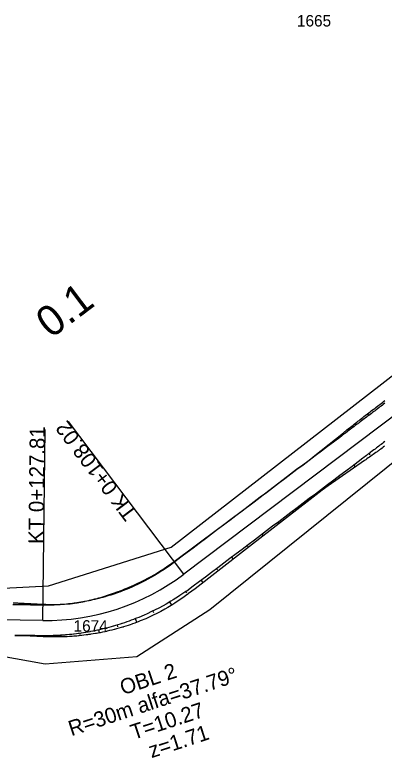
# Model space of a CAD drawing. Extents: x -583470 to -583050, y -1165714 to -1165417.
# Drawn here: x -583308.7 to -583260.4, y -1165593.5 to -1165496.2 of the extents above; entities that cross this region are included whole.
import ezdxf

# ---------------------------------------------------------------- set-up
doc = ezdxf.new("R2010")
doc.units = 0
for name, color, linetype in [('Hranice parcel', 7, 'Continuous'), ('Kabel_soucasny', 7, 'Continuous'), ('Parcelní čísla', 7, 'Continuous'), ('Rám', 7, 'Continuous'), ('Sítě', 7, 'Continuous'), ('Šrafy', 7, 'Continuous')]:
    doc.layers.add(name, color=color, linetype=linetype)

msp = doc.modelspace()

# ---------------------------------------------------------------- linework, layer by layer
at = {"layer": 'Hranice parcel'}
for points in [[(-583286.571, -1165569.38), (-583301.643, -1165549.435)], [(-583305.033, -1165575.443), (-583304.72, -1165550.445)]]:
    msp.add_lwpolyline(points, dxfattribs=at)
at = {"layer": 'Parcelní čísla'}
for p, q in [((-583232.311, -1165528.379), (-583286.571, -1165569.38)), ((-583305.033, -1165575.443), (-583329.322, -1165575.139))]:
    msp.add_line(p, q, dxfattribs=at)
msp.add_arc((-583304.657, -1165545.446), 30, 269.28237, 307.07651, dxfattribs=at)
at = {"layer": 'Rám'}
for points in [[(-583348.01, -1165573.19), (-583304.26, -1165570.92), (-583288.23, -1165565.85), (-583222.91, -1165515.13), (-583194.86, -1165515.1)], [(-583202.69, -1165538.68), (-583225.12, -1165531.51), (-583247.31, -1165545.19), (-583283.21, -1165574.06), (-583292.71, -1165580.22), (-583304.73, -1165581.14), (-583316.86, -1165578.96), (-583335.26, -1165581.29), (-583341.42, -1165583.09), (-583347.21, -1165586.62), (-583351.13, -1165592.35), (-583353.34, -1165595.85), (-583354.98, -1165601.64), (-583352.56, -1165623.43)]]:
    msp.add_lwpolyline(points, dxfattribs=at)
at = {"layer": 'Sítě'}
for points in [[(-583260.31, -1165547.029), (-583260.471, -1165547.151), (-583260.631, -1165547.273), (-583260.634, -1165547.275), (-583260.792, -1165547.394), (-583260.953, -1165547.516), (-583261.114, -1165547.637), (-583261.275, -1165547.759), (-583261.432, -1165547.878), (-583261.436, -1165547.881), (-583261.597, -1165548.002), (-583261.758, -1165548.124), (-583261.919, -1165548.246), (-583262.08, -1165548.367), (-583262.23, -1165548.48), (-583262.241, -1165548.489), (-583262.402, -1165548.611), (-583262.563, -1165548.732), (-583262.724, -1165548.854), (-583262.885, -1165548.975), (-583263.028, -1165549.083), (-583263.046, -1165549.097), (-583263.207, -1165549.219), (-583263.368, -1165549.34), (-583263.529, -1165549.462), (-583263.69, -1165549.584), (-583263.826, -1165549.686), (-583263.851, -1165549.705), (-583264.012, -1165549.827), (-583264.173, -1165549.948), (-583264.334, -1165550.07), (-583264.494, -1165550.192), (-583264.623, -1165550.289), (-583264.655, -1165550.313), (-583264.816, -1165550.435), (-583264.977, -1165550.557), (-583265.138, -1165550.678), (-583265.299, -1165550.8), (-583265.421, -1165550.892), (-583265.46, -1165550.921), (-583265.621, -1165551.043), (-583266.219, -1165551.495), (-583267.017, -1165552.098), (-583267.815, -1165552.701), (-583268.613, -1165553.303), (-583269.41, -1165553.906), (-583270.208, -1165554.509), (-583271.006, -1165555.112), (-583271.804, -1165555.715), (-583272.602, -1165556.318), (-583273.4, -1165556.921), (-583274.197, -1165557.524), (-583274.995, -1165558.127), (-583275.793, -1165558.729), (-583276.591, -1165559.332), (-583277.389, -1165559.935), (-583278.187, -1165560.538), (-583278.984, -1165561.141), (-583279.782, -1165561.744), (-583280.58, -1165562.347), (-583281.378, -1165562.95), (-583282.176, -1165563.552), (-583282.974, -1165564.155), (-583283.771, -1165564.758), (-583284.569, -1165565.361), (-583285.367, -1165565.964), (-583286.165, -1165566.567), (-583286.963, -1165567.17), (-583287.761, -1165567.773), (-583287.777, -1165567.785), (-583288.515, -1165568.324), (-583288.606, -1165568.388), (-583289.287, -1165568.849), (-583289.458, -1165568.961), (-583290.075, -1165569.349), (-583290.33, -1165569.502), (-583290.88, -1165569.821), (-583291.221, -1165570.011), (-583291.7, -1165570.267), (-583292.13, -1165570.487), (-583292.534, -1165570.685), (-583293.055, -1165570.929), (-583293.382, -1165571.075), (-583293.997, -1165571.337), (-583294.243, -1165571.437), (-583294.36, -1165571.483), (-583294.611, -1165571.581), (-583294.863, -1165571.677), (-583294.953, -1165571.71), (-583295.115, -1165571.769), (-583295.116, -1165571.77), (-583295.369, -1165571.86), (-583295.624, -1165571.948), (-583295.879, -1165572.034), (-583295.921, -1165572.048), (-583295.997, -1165572.073), (-583296.135, -1165572.117), (-583296.392, -1165572.198), (-583296.65, -1165572.276), (-583296.889, -1165572.346), (-583296.902, -1165572.35), (-583296.908, -1165572.352), (-583297.167, -1165572.425), (-583297.427, -1165572.496), (-583297.687, -1165572.564), (-583297.79, -1165572.59), (-583297.893, -1165572.616), (-583297.949, -1165572.63), (-583298.21, -1165572.693), (-583298.473, -1165572.754), (-583298.699, -1165572.804), (-583298.736, -1165572.812), (-583298.893, -1165572.846), (-583298.999, -1165572.868), (-583299.263, -1165572.921), (-583299.528, -1165572.972), (-583299.614, -1165572.988), (-583299.793, -1165573.02), (-583299.901, -1165573.039), (-583300.058, -1165573.065), (-583300.324, -1165573.108), (-583300.534, -1165573.14), (-583300.59, -1165573.149), (-583300.857, -1165573.186), (-583300.915, -1165573.194), (-583301.124, -1165573.222), (-583301.391, -1165573.254), (-583301.46, -1165573.262), (-583301.659, -1165573.285), (-583301.926, -1165573.312), (-583301.934, -1165573.313), (-583302.195, -1165573.337), (-583302.389, -1165573.353), (-583302.463, -1165573.359), (-583302.731, -1165573.379), (-583302.957, -1165573.394), (-583303, -1165573.396), (-583303.269, -1165573.411), (-583303.32, -1165573.414), (-583303.538, -1165573.423), (-583303.807, -1165573.433), (-583303.982, -1165573.437), (-583304.076, -1165573.44), (-583304.253, -1165573.443), (-583304.346, -1165573.444), (-583304.615, -1165573.446), (-583304.884, -1165573.445), (-583305.008, -1165573.443), (-583305.164, -1165573.441), (-583305.199, -1165573.441), (-583305.452, -1165573.438), (-583305.741, -1165573.434), (-583306.029, -1165573.431), (-583306.199, -1165573.428), (-583306.318, -1165573.427), (-583306.606, -1165573.423), (-583306.895, -1165573.42), (-583307.183, -1165573.416), (-583307.199, -1165573.416), (-583307.472, -1165573.412), (-583307.761, -1165573.409), (-583308.049, -1165573.405), (-583308.199, -1165573.403), (-583308.338, -1165573.402), (-583308.626, -1165573.398), (-583308.915, -1165573.394)], [(-583308.911, -1165573.139), (-583308.623, -1165573.143), (-583308.334, -1165573.152), (-583308.196, -1165573.159), (-583308.046, -1165573.167), (-583307.758, -1165573.183), (-583307.469, -1165573.199), (-583307.196, -1165573.213), (-583307.181, -1165573.214), (-583306.893, -1165573.227), (-583306.604, -1165573.24), (-583306.316, -1165573.253), (-583306.197, -1165573.259), (-583306.027, -1165573.267), (-583305.739, -1165573.281), (-583305.451, -1165573.295), (-583305.197, -1165573.308), (-583305.162, -1165573.309), (-583305.006, -1165573.317), (-583304.883, -1165573.323), (-583304.615, -1165573.332), (-583304.347, -1165573.34), (-583304.254, -1165573.341), (-583304.078, -1165573.344), (-583303.984, -1165573.345), (-583303.81, -1165573.346), (-583303.541, -1165573.345), (-583303.323, -1165573.342), (-583303.273, -1165573.342), (-583303.004, -1165573.335), (-583302.96, -1165573.334), (-583302.735, -1165573.327), (-583302.466, -1165573.315), (-583302.392, -1165573.312), (-583302.198, -1165573.301), (-583301.937, -1165573.285), (-583301.929, -1165573.284), (-583301.661, -1165573.265), (-583301.461, -1165573.249), (-583301.392, -1165573.243), (-583301.124, -1165573.218), (-583300.915, -1165573.192), (-583300.857, -1165573.183), (-583300.591, -1165573.139), (-583300.536, -1165573.13), (-583300.326, -1165573.093), (-583300.062, -1165573.044), (-583299.905, -1165573.014), (-583299.797, -1165572.993), (-583299.619, -1165572.957), (-583299.534, -1165572.939), (-583299.271, -1165572.883), (-583299.008, -1165572.824), (-583298.903, -1165572.8), (-583298.746, -1165572.763), (-583298.71, -1165572.754), (-583298.485, -1165572.7), (-583298.224, -1165572.634), (-583297.964, -1165572.566), (-583297.909, -1165572.551), (-583297.807, -1165572.523), (-583297.705, -1165572.495), (-583297.447, -1165572.421), (-583297.189, -1165572.345), (-583296.933, -1165572.266), (-583296.914, -1165572.26), (-583296.677, -1165572.185), (-583296.422, -1165572.102), (-583296.167, -1165572.016), (-583296.031, -1165571.969), (-583295.956, -1165571.943), (-583295.914, -1165571.928), (-583295.661, -1165571.838), (-583295.409, -1165571.748), (-583295.157, -1165571.656), (-583294.995, -1165571.596), (-583294.905, -1165571.562), (-583294.655, -1165571.466), (-583294.406, -1165571.368), (-583294.289, -1165571.321), (-583294.045, -1165571.22), (-583293.433, -1165570.959), (-583293.108, -1165570.814), (-583292.588, -1165570.572), (-583292.185, -1165570.376), (-583291.755, -1165570.16), (-583291.276, -1165569.909), (-583290.935, -1165569.724), (-583290.383, -1165569.413), (-583290.128, -1165569.261), (-583289.514, -1165568.874), (-583289.343, -1165568.763), (-583288.665, -1165568.305), (-583288.573, -1165568.242), (-583287.834, -1165567.709), (-583282.205, -1165563.514), (-583281.404, -1165562.915), (-583280.612, -1165562.304), (-583277.393, -1165559.93), (-583276.595, -1165559.327), (-583272.651, -1165556.253), (-583271.852, -1165555.651), (-583271.02, -1165555.094), (-583270.226, -1165554.485), (-583269.445, -1165553.86), (-583265.736, -1165550.891), (-583265.578, -1165550.765), (-583265.54, -1165550.735), (-583265.421, -1165550.639), (-583265.263, -1165550.513), (-583265.105, -1165550.388), (-583264.947, -1165550.262), (-583264.789, -1165550.137), (-583264.757, -1165550.112), (-583264.63, -1165550.012), (-583264.472, -1165549.887), (-583264.313, -1165549.762), (-583264.155, -1165549.638), (-583263.996, -1165549.513), (-583263.971, -1165549.494), (-583263.837, -1165549.389), (-583263.678, -1165549.264), (-583263.519, -1165549.14), (-583263.36, -1165549.016), (-583263.2, -1165548.893), (-583263.182, -1165548.879), (-583263.041, -1165548.769), (-583262.881, -1165548.646), (-583262.722, -1165548.522), (-583262.562, -1165548.399), (-583262.402, -1165548.276), (-583262.391, -1165548.268), (-583262.242, -1165548.153), (-583262.082, -1165548.03), (-583261.921, -1165547.908), (-583261.761, -1165547.786), (-583261.596, -1165547.66), (-583261.44, -1165547.541), (-583261.279, -1165547.419), (-583261.118, -1165547.297), (-583260.958, -1165547.176), (-583260.796, -1165547.054), (-583260.635, -1165546.933), (-583260.474, -1165546.812), (-583260.313, -1165546.691)], [(-583260.312, -1165552.045), (-583260.473, -1165552.167), (-583260.616, -1165552.275), (-583260.634, -1165552.288), (-583260.795, -1165552.41), (-583260.956, -1165552.532), (-583261.117, -1165552.653), (-583261.278, -1165552.775), (-583261.414, -1165552.878), (-583261.439, -1165552.896), (-583261.6, -1165553.018), (-583261.761, -1165553.14), (-583261.922, -1165553.261), (-583262.083, -1165553.383), (-583262.212, -1165553.48), (-583262.244, -1165553.505), (-583262.405, -1165553.626), (-583262.566, -1165553.748), (-583262.727, -1165553.87), (-583262.888, -1165553.991), (-583263.01, -1165554.083), (-583263.049, -1165554.113), (-583263.21, -1165554.234), (-583263.808, -1165554.686), (-583264.605, -1165555.289), (-583265.403, -1165555.892), (-583266.201, -1165556.495), (-583266.999, -1165557.098), (-583267.797, -1165557.701), (-583268.595, -1165558.303), (-583269.392, -1165558.906), (-583270.19, -1165559.509), (-583270.988, -1165560.112), (-583271.786, -1165560.715), (-583272.584, -1165561.318), (-583273.382, -1165561.921), (-583274.179, -1165562.524), (-583274.977, -1165563.127), (-583275.775, -1165563.729), (-583276.573, -1165564.332), (-583277.371, -1165564.935), (-583278.169, -1165565.538), (-583278.966, -1165566.141), (-583279.764, -1165566.744), (-583280.562, -1165567.347), (-583281.36, -1165567.95), (-583282.158, -1165568.552), (-583282.955, -1165569.155), (-583283.753, -1165569.758), (-583284.551, -1165570.361), (-583285.349, -1165570.964), (-583285.365, -1165570.976), (-583286.209, -1165571.592), (-583286.313, -1165571.666), (-583287.091, -1165572.193), (-583287.286, -1165572.32), (-583287.992, -1165572.763), (-583288.283, -1165572.939), (-583288.912, -1165573.304), (-583289.301, -1165573.52), (-583289.849, -1165573.813), (-583290.34, -1165574.064), (-583290.802, -1165574.291), (-583291.398, -1165574.569), (-583291.771, -1165574.736), (-583292.474, -1165575.036), (-583292.755, -1165575.15), (-583292.889, -1165575.203), (-583293.176, -1165575.315), (-583293.464, -1165575.424), (-583293.566, -1165575.462), (-583293.751, -1165575.53), (-583293.752, -1165575.53), (-583294.042, -1165575.634), (-583294.333, -1165575.734), (-583294.625, -1165575.832), (-583294.673, -1165575.848), (-583294.76, -1165575.877), (-583294.918, -1165575.927), (-583295.211, -1165576.02), (-583295.506, -1165576.109), (-583295.78, -1165576.189), (-583295.794, -1165576.194), (-583295.801, -1165576.196), (-583296.097, -1165576.279), (-583296.394, -1165576.36), (-583296.692, -1165576.438), (-583296.809, -1165576.468), (-583296.927, -1165576.498), (-583296.99, -1165576.513), (-583297.289, -1165576.586), (-583297.589, -1165576.655), (-583297.847, -1165576.713), (-583297.89, -1165576.722), (-583298.069, -1165576.76), (-583298.191, -1165576.785), (-583298.492, -1165576.846), (-583298.795, -1165576.904), (-583298.893, -1165576.922), (-583299.098, -1165576.959), (-583299.221, -1165576.98), (-583299.401, -1165577.011), (-583299.705, -1165577.06), (-583299.946, -1165577.097), (-583300.009, -1165577.106), (-583300.314, -1165577.149), (-583300.38, -1165577.158), (-583300.619, -1165577.19), (-583300.924, -1165577.227), (-583301.003, -1165577.236), (-583301.23, -1165577.262), (-583301.536, -1165577.293), (-583301.545, -1165577.294), (-583301.843, -1165577.322), (-583302.064, -1165577.34), (-583302.149, -1165577.347), (-583302.456, -1165577.37), (-583302.714, -1165577.386), (-583302.763, -1165577.389), (-583303.071, -1165577.406), (-583303.129, -1165577.409), (-583303.378, -1165577.42), (-583303.686, -1165577.431), (-583303.885, -1165577.436), (-583303.993, -1165577.439), (-583304.195, -1165577.442), (-583304.301, -1165577.444), (-583304.609, -1165577.446), (-583304.917, -1165577.445), (-583305.058, -1165577.443), (-583305.214, -1165577.441), (-583305.249, -1165577.441), (-583305.503, -1165577.437), (-583305.791, -1165577.434), (-583306.08, -1165577.43), (-583306.249, -1165577.428), (-583306.368, -1165577.427), (-583306.657, -1165577.423), (-583306.945, -1165577.419), (-583307.234, -1165577.416), (-583307.249, -1165577.416), (-583307.522, -1165577.412), (-583307.811, -1165577.409), (-583308.099, -1165577.405), (-583308.249, -1165577.403), (-583308.388, -1165577.401), (-583308.676, -1165577.398)], [(-583260.351, -1165552.664), (-583260.514, -1165552.782), (-583260.678, -1165552.9), (-583260.842, -1165553.018), (-583261.006, -1165553.135), (-583261.144, -1165553.235), (-583261.17, -1165553.253), (-583261.334, -1165553.37), (-583261.498, -1165553.487), (-583261.663, -1165553.604), (-583261.828, -1165553.721), (-583261.96, -1165553.814), (-583261.992, -1165553.837), (-583262.157, -1165553.954), (-583262.322, -1165554.07), (-583262.488, -1165554.186), (-583262.653, -1165554.302), (-583262.778, -1165554.39), (-583262.818, -1165554.418), (-583262.984, -1165554.533), (-583267.706, -1165557.821), (-583268.507, -1165558.42), (-583269.3, -1165559.029), (-583270.091, -1165559.641), (-583277.983, -1165565.784), (-583278.773, -1165566.397), (-583285.115, -1165571.307), (-583285.966, -1165571.937), (-583286.071, -1165572.012), (-583286.856, -1165572.55), (-583287.05, -1165572.687), (-583287.749, -1165573.161), (-583288.039, -1165573.348), (-583288.667, -1165573.737), (-583289.058, -1165573.964), (-583289.611, -1165574.267), (-583290.109, -1165574.526), (-583290.578, -1165574.758), (-583291.183, -1165575.042), (-583291.563, -1165575.211), (-583292.278, -1165575.511), (-583292.565, -1165575.624), (-583292.702, -1165575.677), (-583292.994, -1165575.787), (-583293.288, -1165575.894), (-583293.393, -1165575.932), (-583293.583, -1165575.999), (-583293.878, -1165576.1), (-583294.175, -1165576.197), (-583294.474, -1165576.29), (-583294.523, -1165576.305), (-583294.612, -1165576.332), (-583294.773, -1165576.379), (-583295.073, -1165576.465), (-583295.375, -1165576.548), (-583295.655, -1165576.622), (-583295.677, -1165576.628), (-583295.979, -1165576.704), (-583296.283, -1165576.777), (-583296.587, -1165576.847), (-583296.707, -1165576.874), (-583296.826, -1165576.9), (-583296.891, -1165576.914), (-583297.196, -1165576.978), (-583297.502, -1165577.04), (-583297.765, -1165577.091), (-583297.808, -1165577.099), (-583297.991, -1165577.132), (-583298.115, -1165577.154), (-583298.422, -1165577.206), (-583298.729, -1165577.255), (-583298.83, -1165577.27), (-583299.037, -1165577.3), (-583299.163, -1165577.318), (-583299.346, -1165577.343), (-583299.654, -1165577.382), (-583299.899, -1165577.411), (-583299.963, -1165577.418), (-583300.272, -1165577.451), (-583300.34, -1165577.458), (-583300.582, -1165577.481), (-583300.891, -1165577.507), (-583300.971, -1165577.514), (-583301.201, -1165577.531), (-583301.511, -1165577.551), (-583301.52, -1165577.552), (-583301.821, -1165577.568), (-583302.045, -1165577.578), (-583302.131, -1165577.582), (-583302.441, -1165577.592), (-583302.701, -1165577.599), (-583302.751, -1165577.6), (-583303.061, -1165577.604), (-583303.12, -1165577.605), (-583303.371, -1165577.605), (-583303.681, -1165577.603), (-583303.882, -1165577.601), (-583303.99, -1165577.598), (-583304.193, -1165577.593), (-583304.3, -1165577.59), (-583304.609, -1165577.579), (-583304.918, -1165577.564), (-583305.06, -1165577.556), (-583305.215, -1165577.548), (-583305.25, -1165577.547), (-583305.504, -1165577.533), (-583305.792, -1165577.519), (-583306.08, -1165577.504), (-583306.25, -1165577.496), (-583306.369, -1165577.49), (-583306.657, -1165577.48), (-583306.946, -1165577.475), (-583307.234, -1165577.47), (-583307.249, -1165577.47), (-583307.523, -1165577.466), (-583307.811, -1165577.461), (-583308.1, -1165577.457), (-583308.249, -1165577.455), (-583308.388, -1165577.453), (-583308.677, -1165577.449)]]:
    msp.add_lwpolyline(points, dxfattribs=at)
at = {"layer": 'Šrafy'}
for p, q in [((-583260.53, -1165547.025), (-583260.448, -1165547.134)), ((-583262.601, -1165548.43), (-583262.44, -1165548.639)), ((-583264.503, -1165550.056), (-583264.433, -1165550.145)), ((-583266.528, -1165551.525), (-583266.427, -1165551.652)), ((-583268.451, -1165553.123), (-583268.422, -1165553.16)), ((-583262.242, -1165553.762), (-583262.366, -1165553.597)), ((-583270.435, -1165554.645), (-583270.418, -1165554.668)), ((-583264.169, -1165555.358), (-583264.361, -1165555.104)), ((-583272.436, -1165556.142), (-583272.46, -1165556.109)), ((-583266.289, -1165556.7), (-583266.356, -1165556.612)), ((-583274.434, -1165557.643), (-583274.405, -1165557.681)), ((-583268.261, -1165558.236), (-583268.35, -1165558.119)), ((-583276.403, -1165559.184), (-583276.406, -1165559.18)), ((-583270.294, -1165559.693), (-583270.345, -1165559.626)), ((-583278.407, -1165560.678), (-583278.395, -1165560.695)), ((-583272.217, -1165561.295), (-583272.339, -1165561.133)), ((-583280.404, -1165562.182), (-583280.389, -1165562.202)), ((-583274.262, -1165562.736), (-583274.334, -1165562.64)), ((-583282.413, -1165563.67), (-583282.383, -1165563.709)), ((-583276.163, -1165564.367), (-583276.328, -1165564.148)), ((-583284.398, -1165565.19), (-583284.378, -1165565.217)), ((-583278.229, -1165565.779), (-583278.323, -1165565.655)), ((-583286.423, -1165566.657), (-583286.373, -1165566.724)), ((-583280.112, -1165567.434), (-583280.318, -1165567.162)), ((-583288.406, -1165568.183), (-583288.377, -1165568.224)), ((-583282.201, -1165568.817), (-583282.312, -1165568.669)), ((-583290.533, -1165569.498), (-583290.48, -1165569.589)), ((-583292.725, -1165570.705), (-583292.699, -1165570.762)), ((-583284.067, -1165570.496), (-583284.307, -1165570.176)), ((-583295.055, -1165571.619), (-583295.012, -1165571.732)), ((-583286.194, -1165571.84), (-583286.314, -1165571.666)), ((-583297.414, -1165572.452), (-583297.403, -1165572.489)), ((-583307.332, -1165573.31), (-583307.328, -1165573.206)), ((-583304.831, -1165573.325), (-583304.833, -1165573.445)), ((-583302.33, -1165573.328), (-583302.332, -1165573.308)), ((-583299.853, -1165573.004), (-583299.849, -1165573.029)), ((-583288.173, -1165573.431), (-583288.417, -1165573.017)), ((-583290.505, -1165574.433), (-583290.618, -1165574.2)), ((-583292.718, -1165575.683), (-583292.905, -1165575.209)), ((-583297.595, -1165577.058), (-583297.68, -1165576.675)), ((-583295.196, -1165576.258), (-583295.264, -1165576.035)), ((-583307.624, -1165577.464), (-583307.623, -1165577.411)), ((-583305.123, -1165577.498), (-583305.124, -1165577.442)), ((-583302.611, -1165577.597), (-583302.625, -1165577.38)), ((-583300.117, -1165577.278), (-583300.139, -1165577.124))]:
    msp.add_line(p, q, dxfattribs=at)

# ---------------------------------------------------------------- texts
at = {"layer": 'Hranice parcel'}
for s, height, rotation, p in [('0.1', 4, 37.07651, (-583303.961, -1165538.652)), ('TK 0+108.02', 2, 127.07651, (-583292.6, -1165561.402)), ('KT 0+127.81', 2, 89.28237, (-583304.908, -1165565.444)), ('R=30m alfa=37.79%%d', 2, 18.17944, (-583301.285, -1165590.59)), ('OBL 2', 2, 18.17944, (-583294.549, -1165585.221)), ('  T=10.27', 2, 18.17944, (-583294.569, -1165591.542)), ('   z=1.71', 2, 18.17944, (-583292.935, -1165594.163))]:
    msp.add_text(s, height=height, rotation=rotation, dxfattribs=at).set_placement(p)
at = {"layer": 'Kabel_soucasny'}
for s, p in [('1665', (-583271.801, -1165497.746)), ('1674', (-583300.992, -1165576.906))]:
    msp.add_text(s, height=1.5, dxfattribs=at).set_placement(p)

doc.saveas('drawing.dxf')
